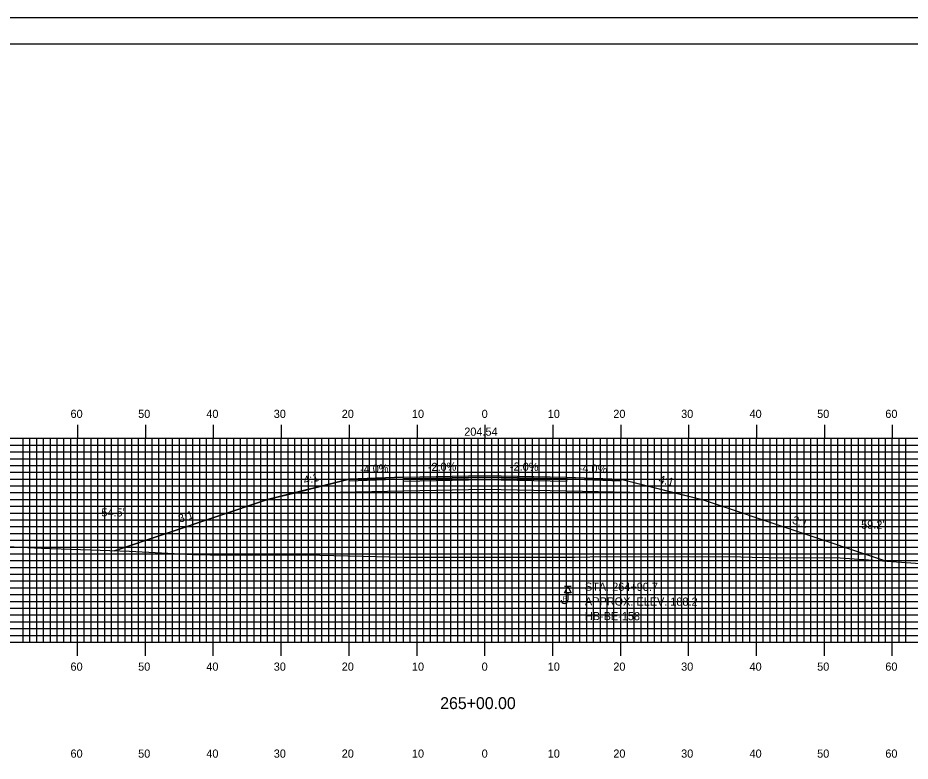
# Model space of a CAD drawing. Extents: x 1807045 to 1807388, y 442591 to 442811.
# Drawn here: x 1807142 to 1807273.4, y 442701.2 to 442810.5 of the extents above; entities that cross this region are included whole.
import ezdxf

# ---------------------------------------------------------------- set-up
doc = ezdxf.new("R2010")
doc.units = 0
for name, color, linetype in [('ANNOTATION', 7, 'Continuous'), ('BORDER', 7, 'Continuous'), ('BORING - REFUSAL', 7, 'Continuous'), ('D_Roadway_Centerline', 7, 'Continuous'), ('D_Roadway_Centerline_Text', 7, 'Continuous'), ('D_Roadway_Edge_Shoulder', 7, 'Continuous'), ('D_Roadway_Edge_TW', 7, 'Continuous'), ('D_Roadway_Pavement', 7, 'Continuous'), ('D_Roadway_SlopeLines', 7, 'Continuous'), ('D_Roadway_SubGrade', 7, 'Continuous'), ('D_Text_Standard', 7, 'Continuous'), ('H_V ANNOTATION', 7, 'Continuous'), ('MAJOR', 7, 'Continuous'), ('MINOR', 7, 'Continuous'), ('PLOT BOUNDARY', 7, 'Continuous'), ('S_Roadway_Centerline', 7, 'Continuous')]:
    doc.layers.add(name, color=color, linetype=linetype)

msp = doc.modelspace()

# ---------------------------------------------------------------- linework, layer by layer
at = {"layer": 'BORDER'}
msp.add_lwpolyline([(1807061.16, 442596.67), (1807381.16, 442596.67), (1807381.16, 442806.67), (1807061.16, 442806.67)], close=True, dxfattribs=at)
at = {"layer": 'BORING - REFUSAL'}
for p, q in [((1807223.44, 442726.87), (1807222.48, 442726.87)), ((1807222.96, 442725.91), (1807222.96, 442724.85))]:
    msp.add_line(p, q, dxfattribs=at)
msp.add_lwpolyline([(1807222.96, 442726.87), (1807223.44, 442725.91), (1807222.48, 442725.91)], close=True, dxfattribs=at)
msp.add_arc((1807222.47, 442724.85), 0.485, 180, 0, dxfattribs=at)
at = {"layer": 'D_Roadway_Centerline'}
for points in [[(1807156.22, 442732.13), (1807178.76, 442739.65), (1807180.58, 442740.1), (1807190.76, 442742.65), (1807198.76, 442742.97), (1807210.76, 442743.21), (1807222.76, 442742.97), (1807230.76, 442742.65), (1807240.93, 442740.1), (1807242.76, 442739.65), (1807269.92, 442730.59)], [(1807156.22, 442732.13), (1807178.76, 442739.65), (1807182.4, 442740.56), (1807190.76, 442742.65), (1807198.76, 442742.97), (1807210.76, 442743.21), (1807222.76, 442742.97), (1807230.76, 442742.65), (1807239.12, 442740.56), (1807242.76, 442739.65), (1807269.92, 442730.59)]]:
    msp.add_lwpolyline(points, dxfattribs=at)
at = {"layer": 'D_Roadway_Edge_Shoulder'}
for points in [[(1807198.76, 442742.97), (1807190.76, 442742.65), (1807190.76, 442742.4), (1807198.76, 442742.72)], [(1807198.76, 442742.97), (1807190.76, 442742.65), (1807190.76, 442742.4), (1807198.76, 442742.72)], [(1807222.76, 442742.97), (1807230.76, 442742.65), (1807230.76, 442742.4), (1807222.76, 442742.72)], [(1807222.76, 442742.97), (1807230.76, 442742.65), (1807230.76, 442742.4), (1807222.76, 442742.72)]]:
    msp.add_lwpolyline(points, close=True, dxfattribs=at)
at = {"layer": 'D_Roadway_Edge_TW'}
msp.add_lwpolyline([(1807198.76, 442742.72), (1807198.76, 442742.97), (1807210.76, 442743.21), (1807222.76, 442742.97), (1807222.76, 442742.72), (1807210.76, 442742.96)], close=True, dxfattribs=at)
msp.add_lwpolyline([(1807198.76, 442742.72), (1807198.76, 442742.97), (1807210.76, 442743.21), (1807222.76, 442742.97), (1807222.76, 442742.72), (1807210.76, 442742.96)], close=True, dxfattribs=at)
at = {"layer": 'D_Roadway_Pavement'}
msp.add_lwpolyline([(1807198.76, 442742.3), (1807198.76, 442742.72), (1807210.76, 442742.96), (1807222.76, 442742.72), (1807222.76, 442742.3), (1807210.76, 442742.54)], close=True, dxfattribs=at)
msp.add_lwpolyline([(1807198.76, 442742.3), (1807198.76, 442742.72), (1807210.76, 442742.96), (1807222.76, 442742.72), (1807222.76, 442742.3), (1807210.76, 442742.54)], close=True, dxfattribs=at)
at = {"layer": 'D_Roadway_SlopeLines'}
for points in [[(1807190.76, 442742.65), (1807178.76, 442739.65), (1807156.22, 442732.13)], [(1807190.76, 442742.65), (1807178.76, 442739.65), (1807156.22, 442732.13)], [(1807230.76, 442742.65), (1807242.76, 442739.65), (1807269.92, 442730.59)], [(1807230.76, 442742.65), (1807242.76, 442739.65), (1807269.92, 442730.59)]]:
    msp.add_lwpolyline(points, dxfattribs=at)
at = {"layer": 'D_Roadway_SubGrade'}
msp.add_lwpolyline([(1807198.76, 442740.88), (1807182.4, 442740.56), (1807190.76, 442742.65), (1807190.76, 442742.4), (1807198.76, 442742.72), (1807210.76, 442742.96), (1807222.76, 442742.72), (1807230.76, 442742.4), (1807230.76, 442742.65), (1807239.12, 442740.56), (1807222.76, 442740.88), (1807210.76, 442741.12)], close=True, dxfattribs=at)
at = {"layer": 'MAJOR'}
for p, q in [((1807150.76, 442750.67), (1807150.76, 442748.67)), ((1807160.76, 442750.67), (1807160.76, 442748.67)), ((1807170.76, 442750.67), (1807170.76, 442748.67)), ((1807180.76, 442750.67), (1807180.76, 442748.67)), ((1807190.76, 442750.67), (1807190.76, 442748.67)), ((1807200.76, 442750.67), (1807200.76, 442748.67)), ((1807210.76, 442750.67), (1807210.76, 442748.67)), ((1807220.76, 442750.67), (1807220.76, 442748.67)), ((1807230.76, 442750.67), (1807230.76, 442748.67)), ((1807240.76, 442750.67), (1807240.76, 442748.67)), ((1807250.76, 442750.67), (1807250.76, 442748.67)), ((1807260.76, 442750.67), (1807260.76, 442748.67)), ((1807270.76, 442750.67), (1807270.76, 442748.67)), ((1807070.76, 442748.67), (1807350.76, 442748.67)), ((1807070.76, 442748.67), (1807350.76, 442748.67)), ((1807150.76, 442718.67), (1807150.76, 442748.67)), ((1807160.76, 442718.67), (1807160.76, 442748.67)), ((1807170.76, 442718.67), (1807170.76, 442748.67)), ((1807180.76, 442718.67), (1807180.76, 442748.67)), ((1807190.76, 442718.67), (1807190.76, 442748.67)), ((1807200.76, 442718.67), (1807200.76, 442748.67)), ((1807210.76, 442718.67), (1807210.76, 442748.67)), ((1807220.76, 442718.67), (1807220.76, 442748.67)), ((1807230.76, 442718.67), (1807230.76, 442748.67)), ((1807240.76, 442718.67), (1807240.76, 442748.67)), ((1807250.76, 442718.67), (1807250.76, 442748.67)), ((1807260.76, 442718.67), (1807260.76, 442748.67)), ((1807270.76, 442718.67), (1807270.76, 442748.67)), ((1807070.76, 442743.67), (1807350.76, 442743.67)), ((1807070.76, 442738.67), (1807350.76, 442738.67)), ((1807070.76, 442733.67), (1807350.76, 442733.67)), ((1807070.76, 442728.67), (1807350.76, 442728.67)), ((1807070.76, 442723.67), (1807350.76, 442723.67)), ((1807070.76, 442718.67), (1807350.76, 442718.67)), ((1807070.76, 442718.67), (1807350.76, 442718.67)), ((1807150.76, 442716.66), (1807150.76, 442718.67)), ((1807160.76, 442716.66), (1807160.76, 442718.67)), ((1807170.76, 442716.66), (1807170.76, 442718.67)), ((1807180.76, 442716.66), (1807180.76, 442718.67)), ((1807190.76, 442716.66), (1807190.76, 442718.67)), ((1807200.76, 442716.66), (1807200.76, 442718.67)), ((1807210.76, 442716.66), (1807210.76, 442718.67)), ((1807220.76, 442716.66), (1807220.76, 442718.67)), ((1807230.76, 442716.66), (1807230.76, 442718.67)), ((1807240.76, 442716.66), (1807240.76, 442718.67)), ((1807250.76, 442716.66), (1807250.76, 442718.67)), ((1807260.76, 442716.66), (1807260.76, 442718.67)), ((1807270.76, 442716.66), (1807270.76, 442718.67))]:
    msp.add_line(p, q, dxfattribs=at)
at = {"layer": 'MINOR'}
for p, q in [((1807070.76, 442747.67), (1807350.76, 442747.67)), ((1807142.76, 442718.67), (1807142.76, 442748.67)), ((1807143.76, 442718.67), (1807143.76, 442748.67)), ((1807144.76, 442718.67), (1807144.76, 442748.67)), ((1807145.76, 442718.67), (1807145.76, 442748.67)), ((1807146.76, 442718.67), (1807146.76, 442748.67)), ((1807147.76, 442718.67), (1807147.76, 442748.67)), ((1807148.76, 442718.67), (1807148.76, 442748.67)), ((1807149.76, 442718.67), (1807149.76, 442748.67)), ((1807151.76, 442718.67), (1807151.76, 442748.67)), ((1807152.76, 442718.67), (1807152.76, 442748.67)), ((1807153.76, 442718.67), (1807153.76, 442748.67)), ((1807154.76, 442718.67), (1807154.76, 442748.67)), ((1807155.76, 442718.67), (1807155.76, 442748.67)), ((1807156.76, 442718.67), (1807156.76, 442748.67)), ((1807157.76, 442718.67), (1807157.76, 442748.67)), ((1807158.76, 442718.67), (1807158.76, 442748.67)), ((1807159.76, 442718.67), (1807159.76, 442748.67)), ((1807161.76, 442718.67), (1807161.76, 442748.67)), ((1807162.76, 442718.67), (1807162.76, 442748.67)), ((1807163.76, 442718.67), (1807163.76, 442748.67)), ((1807164.76, 442718.67), (1807164.76, 442748.67)), ((1807165.76, 442718.67), (1807165.76, 442748.67)), ((1807166.76, 442718.67), (1807166.76, 442748.67)), ((1807167.76, 442718.67), (1807167.76, 442748.67)), ((1807168.76, 442718.67), (1807168.76, 442748.67)), ((1807169.76, 442718.67), (1807169.76, 442748.67)), ((1807171.76, 442718.67), (1807171.76, 442748.67)), ((1807172.76, 442718.67), (1807172.76, 442748.67)), ((1807173.76, 442718.67), (1807173.76, 442748.67)), ((1807174.76, 442718.67), (1807174.76, 442748.67)), ((1807175.76, 442718.67), (1807175.76, 442748.67)), ((1807176.76, 442718.67), (1807176.76, 442748.67)), ((1807177.76, 442718.67), (1807177.76, 442748.67)), ((1807178.76, 442718.67), (1807178.76, 442748.67)), ((1807179.76, 442718.67), (1807179.76, 442748.67)), ((1807181.76, 442718.67), (1807181.76, 442748.67)), ((1807182.76, 442718.67), (1807182.76, 442748.67)), ((1807183.76, 442718.67), (1807183.76, 442748.67)), ((1807184.76, 442718.67), (1807184.76, 442748.67)), ((1807185.76, 442718.67), (1807185.76, 442748.67)), ((1807186.76, 442718.67), (1807186.76, 442748.67)), ((1807187.76, 442718.67), (1807187.76, 442748.67)), ((1807188.76, 442718.67), (1807188.76, 442748.67)), ((1807189.76, 442718.67), (1807189.76, 442748.67)), ((1807191.76, 442718.67), (1807191.76, 442748.67)), ((1807192.76, 442718.67), (1807192.76, 442748.67)), ((1807193.76, 442718.67), (1807193.76, 442748.67)), ((1807194.76, 442718.67), (1807194.76, 442748.67)), ((1807195.76, 442718.67), (1807195.76, 442748.67)), ((1807196.76, 442718.67), (1807196.76, 442748.67)), ((1807197.76, 442718.67), (1807197.76, 442748.67)), ((1807198.76, 442718.67), (1807198.76, 442748.67)), ((1807199.76, 442718.67), (1807199.76, 442748.67)), ((1807201.76, 442718.67), (1807201.76, 442748.67)), ((1807202.76, 442718.67), (1807202.76, 442748.67)), ((1807203.76, 442718.67), (1807203.76, 442748.67)), ((1807204.76, 442718.67), (1807204.76, 442748.67)), ((1807205.76, 442718.67), (1807205.76, 442748.67)), ((1807206.76, 442718.67), (1807206.76, 442748.67)), ((1807207.76, 442718.67), (1807207.76, 442748.67)), ((1807208.76, 442718.67), (1807208.76, 442748.67)), ((1807209.76, 442718.67), (1807209.76, 442748.67)), ((1807211.76, 442718.67), (1807211.76, 442748.67)), ((1807212.76, 442718.67), (1807212.76, 442748.67)), ((1807213.76, 442718.67), (1807213.76, 442748.67)), ((1807214.76, 442718.67), (1807214.76, 442748.67)), ((1807215.76, 442718.67), (1807215.76, 442748.67)), ((1807216.76, 442718.67), (1807216.76, 442748.67)), ((1807217.76, 442718.67), (1807217.76, 442748.67)), ((1807218.76, 442718.67), (1807218.76, 442748.67)), ((1807219.76, 442718.67), (1807219.76, 442748.67)), ((1807221.76, 442718.67), (1807221.76, 442748.67)), ((1807222.76, 442718.67), (1807222.76, 442748.67)), ((1807223.76, 442718.67), (1807223.76, 442748.67)), ((1807224.76, 442718.67), (1807224.76, 442748.67)), ((1807225.76, 442718.67), (1807225.76, 442748.67)), ((1807226.76, 442718.67), (1807226.76, 442748.67)), ((1807227.76, 442718.67), (1807227.76, 442748.67)), ((1807228.76, 442718.67), (1807228.76, 442748.67)), ((1807229.76, 442718.67), (1807229.76, 442748.67)), ((1807231.76, 442718.67), (1807231.76, 442748.67)), ((1807232.76, 442718.67), (1807232.76, 442748.67)), ((1807233.76, 442718.67), (1807233.76, 442748.67)), ((1807234.76, 442718.67), (1807234.76, 442748.67)), ((1807235.76, 442718.67), (1807235.76, 442748.67)), ((1807236.76, 442718.67), (1807236.76, 442748.67)), ((1807237.76, 442718.67), (1807237.76, 442748.67)), ((1807238.76, 442718.67), (1807238.76, 442748.67)), ((1807239.76, 442718.67), (1807239.76, 442748.67)), ((1807241.76, 442718.67), (1807241.76, 442748.67)), ((1807242.76, 442718.67), (1807242.76, 442748.67)), ((1807243.76, 442718.67), (1807243.76, 442748.67)), ((1807244.76, 442718.67), (1807244.76, 442748.67)), ((1807245.76, 442718.67), (1807245.76, 442748.67)), ((1807246.76, 442718.67), (1807246.76, 442748.67)), ((1807247.76, 442718.67), (1807247.76, 442748.67)), ((1807248.76, 442718.67), (1807248.76, 442748.67)), ((1807249.76, 442718.67), (1807249.76, 442748.67)), ((1807251.76, 442718.67), (1807251.76, 442748.67)), ((1807252.76, 442718.67), (1807252.76, 442748.67)), ((1807253.76, 442718.67), (1807253.76, 442748.67)), ((1807254.76, 442718.67), (1807254.76, 442748.67)), ((1807255.76, 442718.67), (1807255.76, 442748.67)), ((1807256.76, 442718.67), (1807256.76, 442748.67)), ((1807257.76, 442718.67), (1807257.76, 442748.67)), ((1807258.76, 442718.67), (1807258.76, 442748.67)), ((1807259.76, 442718.67), (1807259.76, 442748.67)), ((1807261.76, 442718.67), (1807261.76, 442748.67)), ((1807262.76, 442718.67), (1807262.76, 442748.67)), ((1807263.76, 442718.67), (1807263.76, 442748.67)), ((1807264.76, 442718.67), (1807264.76, 442748.67)), ((1807265.76, 442718.67), (1807265.76, 442748.67)), ((1807266.76, 442718.67), (1807266.76, 442748.67)), ((1807267.76, 442718.67), (1807267.76, 442748.67)), ((1807268.76, 442718.67), (1807268.76, 442748.67)), ((1807269.76, 442718.67), (1807269.76, 442748.67)), ((1807271.76, 442718.67), (1807271.76, 442748.67)), ((1807272.76, 442718.67), (1807272.76, 442748.67)), ((1807070.76, 442746.67), (1807350.76, 442746.67)), ((1807070.76, 442745.67), (1807350.76, 442745.67)), ((1807070.76, 442744.67), (1807350.76, 442744.67)), ((1807070.76, 442742.67), (1807350.76, 442742.67)), ((1807070.76, 442741.67), (1807350.76, 442741.67)), ((1807070.76, 442740.67), (1807350.76, 442740.67)), ((1807070.76, 442739.67), (1807350.76, 442739.67)), ((1807070.76, 442737.67), (1807350.76, 442737.67)), ((1807070.76, 442736.67), (1807350.76, 442736.67)), ((1807070.76, 442735.67), (1807350.76, 442735.67)), ((1807070.76, 442734.67), (1807350.76, 442734.67)), ((1807070.76, 442732.67), (1807350.76, 442732.67)), ((1807070.76, 442731.67), (1807350.76, 442731.67)), ((1807070.76, 442730.67), (1807350.76, 442730.67)), ((1807070.76, 442729.67), (1807350.76, 442729.67)), ((1807070.76, 442727.67), (1807350.76, 442727.67)), ((1807070.76, 442726.67), (1807350.76, 442726.67)), ((1807070.76, 442725.67), (1807350.76, 442725.67)), ((1807070.76, 442724.67), (1807350.76, 442724.67)), ((1807070.76, 442722.67), (1807350.76, 442722.67)), ((1807070.76, 442721.67), (1807350.76, 442721.67)), ((1807070.76, 442720.67), (1807350.76, 442720.67)), ((1807070.76, 442719.67), (1807350.76, 442719.67))]:
    msp.add_line(p, q, dxfattribs=at)
at = {"layer": 'PLOT BOUNDARY'}
msp.add_lwpolyline([(1807044.97, 442590.55), (1807384.97, 442590.55), (1807384.97, 442810.55), (1807044.97, 442810.55)], close=True, dxfattribs=at)
at = {"layer": 'S_Roadway_Centerline'}
msp.add_lwpolyline([(1807070.76, 442734), (1807077.35, 442733.71), (1807083.9, 442733.68), (1807088.67, 442733.68), (1807104.46, 442733.12), (1807108.52, 442733.27), (1807119.52, 442732.72), (1807125.53, 442732.76), (1807134.32, 442733.04), (1807145.45, 442732.49), (1807158.42, 442732.06), (1807167.83, 442731.58), (1807170.31, 442731.53), (1807173.41, 442731.52), (1807186.45, 442731.49), (1807198.87, 442731.18), (1807223.95, 442731.18), (1807228.51, 442731.27), (1807248.47, 442731.22), (1807250.1, 442731.17), (1807252.52, 442731.12), (1807263.1, 442731.07), (1807274.86, 442730.25)], dxfattribs=at)

# ---------------------------------------------------------------- texts
at = {"layer": 'ANNOTATION'}
for s, rotation, p in [('-4.0%', 2.2906, (1807192.39, 442743.51)), ('-2.0%', 1.1458, (1807202.36, 442743.84)), ('-2.0%', 358.8542, (1807214.44, 442743.93)), ('-4.0%', 357.7094, (1807224.55, 442743.7)), ('4:1', 14.0362, (1807184.21, 442741.87)), ('4:1', 345.9638, (1807236.26, 442742.13)), ('3:1', 18.4348, (1807165.83, 442736.24)), ('3:1', 18.4348, (1807165.83, 442736.24)), ('3:1', 341.5652, (1807255.94, 442736.16)), ('3:1', 341.5652, (1807255.94, 442736.16))]:
    msp.add_text(s, height=1.2, rotation=rotation, dxfattribs=at).set_placement(p)
at = {"layer": 'BORING - REFUSAL'}
for s, p in [('STA. 264+90.7', (1807225.49, 442726.24)), ('APPROX. ELEV. 188.2', (1807225.49, 442724.08)), ('HB-BE-158', (1807225.48, 442721.92))]:
    msp.add_text(s, height=1.2, rotation=359.8142, dxfattribs=at).set_placement(p)
msp.add_text('R', height=0.64, dxfattribs=at).set_placement((1807222.25, 442724.79))
at = {"layer": 'D_Roadway_Centerline'}
for s, p in [('C', (1807210.75, 442743.21)), ('C', (1807210.75, 442743.21)), ('L', (1807210.76, 442743.2)), ('L', (1807210.76, 442743.2))]:
    msp.add_text(s, height=0.0146, dxfattribs=at).set_placement(p)
at = {"layer": 'D_Roadway_Centerline_Text'}
msp.add_text('204.54', height=1.2, dxfattribs=at).set_placement((1807207.72, 442749.05))
at = {"layer": 'D_Text_Standard'}
for s, p in [("-54.5'", (1807153.74, 442737.17)), ("59.2'", (1807266.17, 442735.36))]:
    msp.add_text(s, height=1.2, dxfattribs=at).set_placement(p)
at = {"layer": 'H_V ANNOTATION'}
for s, height, p in [('60', 1.2, (1807149.73, 442751.67)), ('50', 1.2, (1807159.69, 442751.67)), ('40', 1.2, (1807169.73, 442751.67)), ('30', 1.2, (1807179.66, 442751.67)), ('20', 1.2, (1807189.67, 442751.67)), ('10', 1.2, (1807200.01, 442751.67)), ('0', 1.2, (1807210.28, 442751.67)), ('10', 1.2, (1807220.01, 442751.67)), ('20', 1.2, (1807229.67, 442751.67)), ('30', 1.2, (1807239.66, 442751.67)), ('40', 1.2, (1807249.73, 442751.67)), ('50', 1.2, (1807259.69, 442751.67)), ('60', 1.2, (1807269.73, 442751.67)), ('60', 1.2, (1807149.73, 442714.47)), ('50', 1.2, (1807159.69, 442714.47)), ('40', 1.2, (1807169.73, 442714.47)), ('30', 1.2, (1807179.66, 442714.47)), ('20', 1.2, (1807189.67, 442714.47)), ('10', 1.2, (1807200.01, 442714.47)), ('0', 1.2, (1807210.28, 442714.47)), ('10', 1.2, (1807220.01, 442714.47)), ('20', 1.2, (1807229.67, 442714.47)), ('30', 1.2, (1807239.66, 442714.47)), ('40', 1.2, (1807249.73, 442714.47)), ('50', 1.2, (1807259.69, 442714.47)), ('60', 1.2, (1807269.73, 442714.47)), ('265+00.00', 1.75, (1807204.17, 442708.82)), ('60', 1.2, (1807149.73, 442701.67)), ('50', 1.2, (1807159.69, 442701.67)), ('40', 1.2, (1807169.73, 442701.67)), ('30', 1.2, (1807179.66, 442701.67)), ('20', 1.2, (1807189.67, 442701.67)), ('10', 1.2, (1807200.01, 442701.67)), ('0', 1.2, (1807210.28, 442701.67)), ('10', 1.2, (1807220.01, 442701.67)), ('20', 1.2, (1807229.67, 442701.67)), ('30', 1.2, (1807239.66, 442701.67)), ('40', 1.2, (1807249.73, 442701.67)), ('50', 1.2, (1807259.69, 442701.67)), ('60', 1.2, (1807269.73, 442701.67))]:
    msp.add_text(s, height=height, dxfattribs=at).set_placement(p)

doc.saveas('drawing.dxf')
